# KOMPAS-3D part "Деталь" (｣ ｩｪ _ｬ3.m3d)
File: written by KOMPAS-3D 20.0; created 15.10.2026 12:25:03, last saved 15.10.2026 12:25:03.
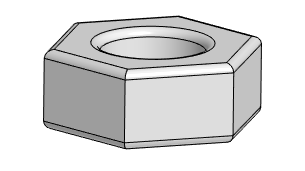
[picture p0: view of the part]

Document properties: Полное имя файла: D:\RicWork\Project-EPS32\box_compas\прочее\гайка_м3.m3d

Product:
- Part/product: Деталь
    Масса: 0.000354634

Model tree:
1. Эскиз:1
2. Элемент выдавливания:1
     Расстояние 1 = 2.4
3. Скругление:1  (with: Элемент выдавливания:1)
     Радиус = 0.25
